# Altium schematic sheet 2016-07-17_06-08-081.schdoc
size 231 x 111 mm; SheetNumber: 1; SheetTotal: 1
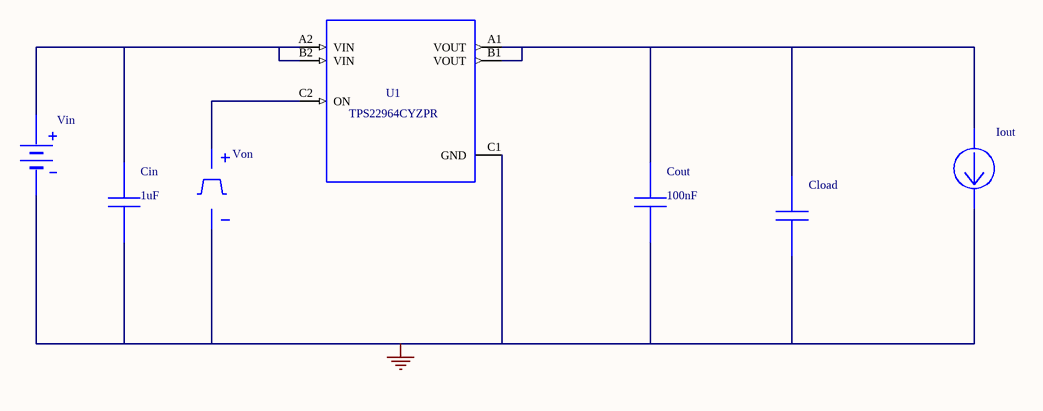
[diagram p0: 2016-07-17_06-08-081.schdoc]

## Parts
Cin  value 1uF  (hidden comment: C0603C105Z9VACTU)
Cload  GRM21BR71E104KA01L  (value not drawn)
Cout  value 100nF  (hidden comment: GRM155R60J104KA01D)
Iout  WB_CURRENT_LOAD  (value not drawn)
U1  TPS22964CYZPR
Vin  WB_BATTERY  (value not drawn)
Von  WB_PRIM_PWL_VOLTAGE_SOURCE  (value not drawn)

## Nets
0: Cin.2 Cload.2 Cout.2 Iout.2(-) U1.C1(GND) Vin.2(-) Von.2(-)
NetCin_1: Cin.1 U1.A2(VIN) U1.B2(VIN) Vin.1(+)
NetCload_1: Cload.1 Cout.1 Iout.1(+) U1.A1(VOUT) U1.B1(VOUT)
NetU1_C2: U1.C2(ON) Von.1(+)

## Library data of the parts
Cin = C0603C105Z9VACTU: Manufacturer Name: Kemet
Cload = GRM21BR71E104KA01L: WB_PRIMITIVE_CAP; Manufacturer Name: WB_PRIMITIVE_CAPACITOR
Cout = GRM155R60J104KA01D: GRM155R60J104KA0; Manufacturer Name: MuRata
U1 = TPS22964CYZPR: Manufacturer Name: Texas Instruments
Von = WB_PRIM_PWL_VOLTAGE_SOURCE: WB_PRIM_PWL_VOLT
